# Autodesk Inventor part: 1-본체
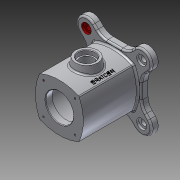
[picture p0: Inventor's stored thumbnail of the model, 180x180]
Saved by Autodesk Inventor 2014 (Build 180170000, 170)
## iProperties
Created: 2016-05
Part Number: 1-본체
Material: 알루미늄 6061
Document SubType Name: Modeling
Designer: Administrator
Density: 2.71 g/cm^3
Appearance: 알루미늄 - 평지
Mass: 1114.45 g
Surface Area: 865.598 cm^2
Volume: 411.237 cm^3
Author: Administrator
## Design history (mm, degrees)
sketch "스케치1"
  geometry: L1 (35.355, 35.355)-(-35.355, 35.355); L2 (-35.355, 35.355)-(-35.355, -35.355); L3 (-35.355, -35.355)-(35.355, -35.355); L4 (35.355, -35.355)-(35.355, 35.355); L5 (35.355, 35.355)-(-35.355, -35.355); L6 (-35.355, 35.355)-(35.355, -35.355); A1 r 85.579 centre (42.579, 0) between (-35.355, 35.355) and (-35.355, -35.355); A2 r 85.579 centre (0, -42.579) between (35.355, 35.355) and (-35.355, 35.355); A3 r 85.579 centre (-42.579, 0) between (35.355, -35.355) and (35.355, 35.355); A4 r 85.579 centre (0, 42.579) between (-35.355, -35.355) and (35.355, -35.355); 3 further points
  constraints: 12 end point, 8 point on circle, 4 centre point, 3 equal radius, 3 midpoint, 2 parallel, 1 coincident, 1 horizontal, 1 perpendicular
  dimensions: "d1" = 100 distance of L2.end L1.start; "d2" = 100 distance of L1.end L3.end (derived); "d3" = 45 deg angle of L6 L1; "d4" = 86 dimension on A1 A3
extrude "돌출1" new body sketch "스케치1" stored distance "d5" = 98; taper "d6" = 0 deg
sketch "스케치2"
  geometry: L1 (49, 49)-(-49, 49); L2 (-49, 49)-(-49, -49); L3 (-49, -49)-(49, -49); L4 (49, -49)-(49, 49); L5 (49, 49)-(-49, -49); L6 (-49, 49)-(49, -49); L7 (23.544, -49)-(36.77, -62.225); L8 (49, -23.544)-(62.225, -36.77); L9 (-23.544, -49)-(-36.77, -62.225); L10 (-49, -23.544)-(-62.225, -36.77); L11 (-49, 23.544)-(-62.225, 36.77); L12 (-23.544, 49)-(-36.77, 62.225); L13 (23.544, 49)-(36.77, 62.225); L14 (49, 23.544)-(62.225, 36.77); A1 r 18 centre (-49.497, -49.497) between (-36.77, -62.225) and (-62.225, -36.77); A2 r 70 centre (0, 0) between (-49.497, 49.497) and (49.497, -49.497); A3 r 18 centre (49.497, -49.497) between (36.77, -62.225) and (62.225, -36.77); A4 r 18 centre (49.497, 49.497) between (36.77, 62.225) and (62.225, 36.77); A5 r 18 centre (-49.497, 49.497) between (-62.225, 36.77) and (-36.77, 62.225); 1 further point
  constraints: 28 end point, 12 point on line, 11 point on circle, 8 tangent, 6 equal length, 5 centre point, 4 parallel, 3 equal radius, 2 midpoint, 1 coincident, 1 horizontal, 1 perpendicular
  dimensions: "d7" = 98 distance of L1.start L1.end; "d8" = 45 deg angle of L3 L5; "d62" = 70 distance of point (0, 0) A1.centre; "d64" = 18 radius of A1; "d66" = 70 radius of A2; "d76" = 98.99495 distance of A2.end A1.centre (derived); "d77" = 98.99495 distance of A2.start A1.centre (derived)
extrude "돌출2" join sketch "스케치2" distance "d13" = 12; taper "d14" = 0 deg
node "작업 평면3"
sketch "스케치5"
  geometry: C1 r 20 at (0, 0); 1 further point
  constraints: 1 centre point, 1 coincident
  dimensions: "d21" = 40 diameter of C1
extrude "돌출3" join sketch "스케치5" stored distance "d22" = 12; taper "d23" = 10 deg
sketch "스케치8"
  geometry: 1 further point
hole "구멍1" sketch "스케치8" at (0, 0) diameter "d24" = 50; stored, may be unused: countersink angle "d28" = 90 deg, drill point angle "d30" = 118 deg; dims "d25" = 6, "d26" = 4, "d27" = 2, "d29" = 8
sketch "스케치9"
  geometry: L1 (-37, 35)-(49, 35); L2 (49, 35)-(49, 0); L3 (49, 0)-(-37, 0); L4 (-37, 0)-(-37, 35); L5 (-49, -25)-(-49, 25) reference; L6 (61, -23.544)-(61, 23.544) reference; 5 further points
  constraints: 8 end point, 2 parallel, 1 horizontal, 1 perpendicular, 1 point on line
  dimensions: "d33" = 12 distance between parallel lines of L5 L4; "d34" = 12 distance between parallel lines of L6 L2; "d35" = 70 diameter of L1 L3
revolve "회전1" sketch "스케치9" stored, may be unused: angle "d36" = 90 deg
sketch "스케치10"
  geometry: L1 (0, 0)-(-28.284, 28.284); L2 (0, -93.8)-(0, 93.8) reference
  constraints: 2 end point
  dimensions: "d38" = 40 distance of L1.start L1.end; "d39" = 45 deg angle of L2 L1
hole "구멍2" sketch "스케치10" at (-28.284, 28.284) diameter "d40" = 3.242; stored, may be unused: countersink angle "d44" = 90 deg, drill point angle "d46" = 118 deg; dims "d41" = 7, "d42" = 4, "d43" = 2, "d45" = 10
sketch "스케치11"
  geometry: L1 (0, 0)-(28.284, -28.284); L2 (0, 94.496)-(0, -94.496) reference
  constraints: 2 end point
  dimensions: "d50" = 45 deg angle of L2 L1; "d51" = 40 distance of L1.start L1.end
hole "구멍3" sketch "스케치11" at (28.284, -28.284) diameter "d52" = 3.242; stored, may be unused: countersink angle "d56" = 90 deg, drill point angle "d58" = 118 deg; dims "d53" = 7, "d54" = 4, "d55" = 2, "d57" = 10
hole "구멍4" diameter "d69" = 10; stored, may be unused: countersink angle "d73" = 90 deg, drill point angle "d75" = 118 deg; dims "d67" = 10, "d68" = 10, "d70" = 7, "d71" = 18, "d72" = 4, "d74" = 10
hole "구멍5" diameter "d86" = 25; stored, may be unused: countersink angle "d90" = 90 deg, drill point angle "d92" = 118 deg; dims "d84" = 10, "d85" = 10, "d87" = 7, "d88" = 30, "d89" = 8, "d91" = 10
fillet "모깎기2" dims "d93" = 3
fillet "모깎기3" dims "d94" = 25
fillet "모깎기4" dims "d95" = 3
chamfer "모따기1" distance "d96" = 1; stored, may be unused: second distance "d97" = 2, angle "d98" = 45 deg
node "작업 평면7"
sketch "스케치15"
  geometry: L1 (-34.285, -49)-(34.285, -49) reference; 2 further points
  constraints: 1 other
  dimensions: "d107" = 29 distance of point (29, 0) point (0, 0); "d108" = 49 distance from line of L1 point (29, 0)
feature "엠보싱3" sketch "스케치15" dims "d1" = 100, "d2" = 100 (derived), "d3" = 45 deg, "d4" = 86, "d109" = 0.5, "d110" = 0
node "솔리드1"
pattern_circular "원형 패턴1" dims angle "d48" = 360 deg
pattern_circular "원형 패턴2" dims angle "d60" = 360 deg
pattern_linear "직사각형 패턴1" dims "d80" = 98.99495 (= d76), "d83" = 98.99495 (= d77)
other parameters: "d20" = 55
